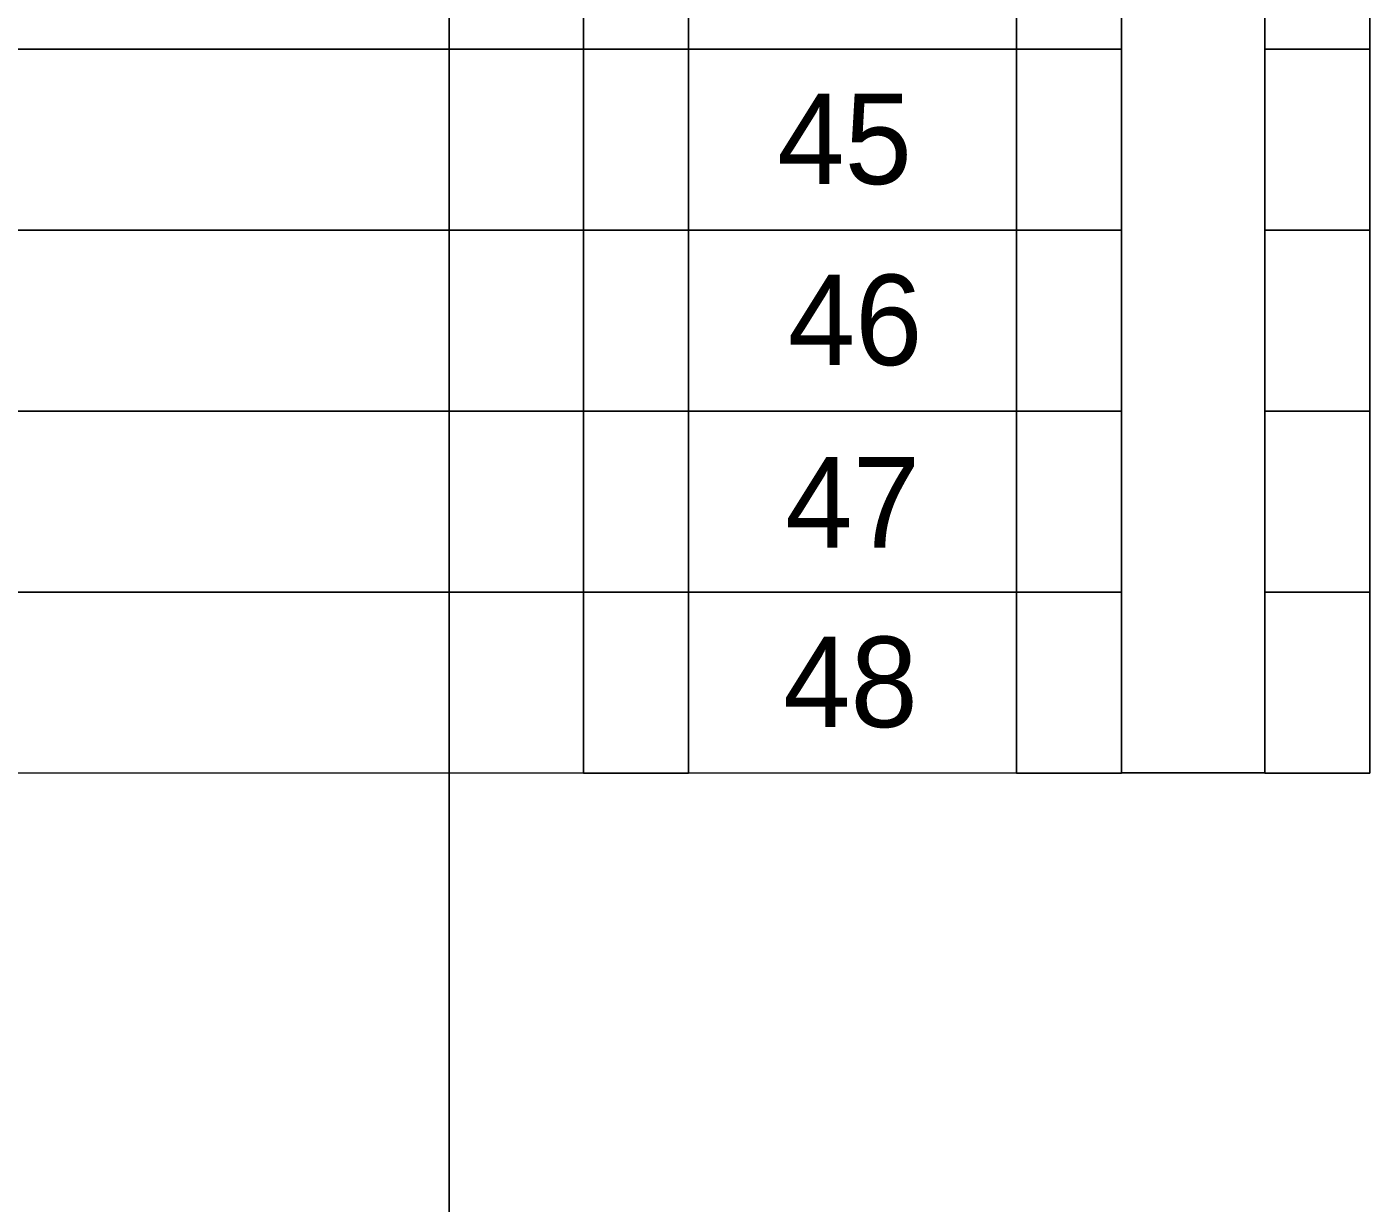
# Model space of a CAD drawing. Extents: x 1901 to 2519, y -3585 to -3154.
# Drawn here: x 2006.66 to 2032.79, y -3380.31 to -3357.44 of the extents above; entities that cross this region are included whole.
import ezdxf

# ---------------------------------------------------------------- set-up
doc = ezdxf.new("R2010")
doc.units = 0
doc.layers.add('rozvláknění', color=7, linetype='Continuous')

msp = doc.modelspace()

# ---------------------------------------------------------------- linework, layer by layer
at = {"layer": 'rozvláknění'}
for p, q in [((1933.193, -3357.872), (2025.898, -3357.874)), ((1933.193, -3361.39), (2025.898, -3361.392)), ((1933.193, -3364.908), (2025.898, -3364.91)), ((1933.193, -3368.426), (2025.898, -3368.428)), ((1933.193, -3371.945), (2025.898, -3371.947))]:
    msp.add_line(p, q, dxfattribs=at)
for points in [[(2014.869, -3178.545), (2059.522, -3178.544), (2059.522, -3570.656), (2014.869, -3570.656)], [(2019.518, -3371.947), (2017.476, -3371.947), (2017.476, -3329.728), (2019.518, -3329.728)], [(2027.939, -3329.728), (2030.726, -3329.728), (2030.726, -3371.943), (2027.939, -3371.943)], [(2025.898, -3354.356), (2027.939, -3354.356), (2027.939, -3357.874), (2025.898, -3357.874)], [(2030.726, -3354.356), (2032.767, -3354.356), (2032.767, -3357.874), (2030.726, -3357.874)], [(2030.726, -3354.356), (2032.767, -3354.356), (2032.767, -3357.874), (2030.726, -3357.874)], [(2025.898, -3357.874), (2027.939, -3357.874), (2027.939, -3361.392), (2025.898, -3361.392)], [(2030.726, -3357.874), (2032.767, -3357.874), (2032.767, -3361.392), (2030.726, -3361.392)], [(2030.726, -3357.874), (2032.767, -3357.874), (2032.767, -3361.392), (2030.726, -3361.392)], [(2025.898, -3361.392), (2027.939, -3361.392), (2027.939, -3364.91), (2025.898, -3364.91)], [(2030.726, -3361.392), (2032.767, -3361.392), (2032.767, -3364.91), (2030.726, -3364.91)], [(2030.726, -3361.392), (2032.767, -3361.392), (2032.767, -3364.91), (2030.726, -3364.91)], [(2025.898, -3364.91), (2027.939, -3364.91), (2027.939, -3368.428), (2025.898, -3368.428)], [(2030.726, -3364.91), (2032.767, -3364.91), (2032.767, -3368.428), (2030.726, -3368.428)], [(2030.726, -3364.91), (2032.767, -3364.91), (2032.767, -3368.428), (2030.726, -3368.428)], [(2025.898, -3368.428), (2027.939, -3368.428), (2027.939, -3371.947), (2025.898, -3371.947)], [(2030.726, -3368.428), (2032.767, -3368.428), (2032.767, -3371.947), (2030.726, -3371.947)], [(2030.726, -3368.428), (2032.767, -3368.428), (2032.767, -3371.947), (2030.726, -3371.947)]]:
    msp.add_lwpolyline(points, close=True, dxfattribs=at)
for points in [[(2019.518, -3329.728), (2017.476, -3329.728), (2017.476, -3371.947), (2019.518, -3371.947), (2019.518, -3329.728)], [(2019.518, -3329.728), (2017.476, -3329.728), (2017.476, -3371.947), (2019.518, -3371.947), (2019.518, -3329.728)], [(2019.518, -3329.728), (2017.476, -3329.728), (2017.476, -3371.947), (2019.518, -3371.947), (2019.518, -3329.728)], [(2019.518, -3329.728), (2017.476, -3329.728), (2017.476, -3371.947), (2019.518, -3371.947), (2019.518, -3329.728)], [(2019.518, -3329.728), (2017.476, -3329.728), (2017.476, -3371.947), (2019.518, -3371.947), (2019.518, -3329.728)], [(2019.518, -3329.728), (2017.476, -3329.728), (2017.476, -3371.947), (2019.518, -3371.947), (2019.518, -3329.728)], [(2025.898, -3357.874), (2027.939, -3357.874), (2027.939, -3354.356), (2025.898, -3354.356), (2025.898, -3357.874)], [(2025.898, -3357.874), (2027.939, -3357.874), (2027.939, -3354.356), (2025.898, -3354.356), (2025.898, -3357.874)], [(2025.898, -3357.874), (2027.939, -3357.874), (2027.939, -3354.356), (2025.898, -3354.356), (2025.898, -3357.874)], [(2025.898, -3357.874), (2027.939, -3357.874), (2027.939, -3354.356), (2025.898, -3354.356), (2025.898, -3357.874)], [(2025.898, -3357.874), (2027.939, -3357.874), (2027.939, -3354.356), (2025.898, -3354.356), (2025.898, -3357.874)], [(2025.898, -3357.874), (2027.939, -3357.874), (2027.939, -3354.356), (2025.898, -3354.356), (2025.898, -3357.874)], [(2025.898, -3357.874), (2027.939, -3357.874), (2027.939, -3354.356), (2025.898, -3354.356), (2025.898, -3357.874)], [(2025.898, -3357.874), (2027.939, -3357.874), (2027.939, -3354.356), (2025.898, -3354.356), (2025.898, -3357.874)], [(2025.898, -3357.874), (2027.939, -3357.874), (2027.939, -3354.356), (2025.898, -3354.356), (2025.898, -3357.874)], [(2025.898, -3357.874), (2027.939, -3357.874), (2027.939, -3354.356), (2025.898, -3354.356), (2025.898, -3357.874)], [(2030.726, -3357.874), (2032.767, -3357.874), (2032.767, -3354.356), (2030.726, -3354.356), (2030.726, -3357.874)], [(2030.726, -3357.874), (2032.767, -3357.874), (2032.767, -3354.356), (2030.726, -3354.356), (2030.726, -3357.874)], [(2030.726, -3357.874), (2032.767, -3357.874), (2032.767, -3354.356), (2030.726, -3354.356), (2030.726, -3357.874)], [(2030.726, -3357.874), (2032.767, -3357.874), (2032.767, -3354.356), (2030.726, -3354.356), (2030.726, -3357.874)], [(2030.726, -3357.874), (2032.767, -3357.874), (2032.767, -3354.356), (2030.726, -3354.356), (2030.726, -3357.874)], [(2030.726, -3357.874), (2032.767, -3357.874), (2032.767, -3354.356), (2030.726, -3354.356), (2030.726, -3357.874)], [(2030.726, -3357.874), (2032.767, -3357.874), (2032.767, -3354.356), (2030.726, -3354.356), (2030.726, -3357.874)], [(2030.726, -3357.874), (2032.767, -3357.874), (2032.767, -3354.356), (2030.726, -3354.356), (2030.726, -3357.874)], [(2030.726, -3357.874), (2032.767, -3357.874), (2032.767, -3354.356), (2030.726, -3354.356), (2030.726, -3357.874)], [(2030.726, -3357.874), (2032.767, -3357.874), (2032.767, -3354.356), (2030.726, -3354.356), (2030.726, -3357.874)], [(2025.898, -3361.392), (2027.939, -3361.392), (2027.939, -3357.874), (2025.898, -3357.874), (2025.898, -3361.392)], [(2025.898, -3361.392), (2027.939, -3361.392), (2027.939, -3357.874), (2025.898, -3357.874), (2025.898, -3361.392)], [(2025.898, -3361.392), (2027.939, -3361.392), (2027.939, -3357.874), (2025.898, -3357.874), (2025.898, -3361.392)], [(2025.898, -3361.392), (2027.939, -3361.392), (2027.939, -3357.874), (2025.898, -3357.874), (2025.898, -3361.392)], [(2025.898, -3361.392), (2027.939, -3361.392), (2027.939, -3357.874), (2025.898, -3357.874), (2025.898, -3361.392)], [(2025.898, -3361.392), (2027.939, -3361.392), (2027.939, -3357.874), (2025.898, -3357.874), (2025.898, -3361.392)], [(2025.898, -3361.392), (2027.939, -3361.392), (2027.939, -3357.874), (2025.898, -3357.874), (2025.898, -3361.392)], [(2025.898, -3361.392), (2027.939, -3361.392), (2027.939, -3357.874), (2025.898, -3357.874), (2025.898, -3361.392)], [(2025.898, -3361.392), (2027.939, -3361.392), (2027.939, -3357.874), (2025.898, -3357.874), (2025.898, -3361.392)], [(2025.898, -3361.392), (2027.939, -3361.392), (2027.939, -3357.874), (2025.898, -3357.874), (2025.898, -3361.392)], [(2030.726, -3361.392), (2032.767, -3361.392), (2032.767, -3357.874), (2030.726, -3357.874), (2030.726, -3361.392)], [(2030.726, -3361.392), (2032.767, -3361.392), (2032.767, -3357.874), (2030.726, -3357.874), (2030.726, -3361.392)], [(2030.726, -3361.392), (2032.767, -3361.392), (2032.767, -3357.874), (2030.726, -3357.874), (2030.726, -3361.392)], [(2030.726, -3361.392), (2032.767, -3361.392), (2032.767, -3357.874), (2030.726, -3357.874), (2030.726, -3361.392)], [(2030.726, -3361.392), (2032.767, -3361.392), (2032.767, -3357.874), (2030.726, -3357.874), (2030.726, -3361.392)], [(2030.726, -3361.392), (2032.767, -3361.392), (2032.767, -3357.874), (2030.726, -3357.874), (2030.726, -3361.392)], [(2030.726, -3361.392), (2032.767, -3361.392), (2032.767, -3357.874), (2030.726, -3357.874), (2030.726, -3361.392)], [(2030.726, -3361.392), (2032.767, -3361.392), (2032.767, -3357.874), (2030.726, -3357.874), (2030.726, -3361.392)], [(2030.726, -3361.392), (2032.767, -3361.392), (2032.767, -3357.874), (2030.726, -3357.874), (2030.726, -3361.392)], [(2030.726, -3361.392), (2032.767, -3361.392), (2032.767, -3357.874), (2030.726, -3357.874), (2030.726, -3361.392)], [(2025.898, -3364.91), (2027.939, -3364.91), (2027.939, -3361.392), (2025.898, -3361.392), (2025.898, -3364.91)], [(2025.898, -3364.91), (2027.939, -3364.91), (2027.939, -3361.392), (2025.898, -3361.392), (2025.898, -3364.91)], [(2025.898, -3364.91), (2027.939, -3364.91), (2027.939, -3361.392), (2025.898, -3361.392), (2025.898, -3364.91)], [(2025.898, -3364.91), (2027.939, -3364.91), (2027.939, -3361.392), (2025.898, -3361.392), (2025.898, -3364.91)], [(2025.898, -3364.91), (2027.939, -3364.91), (2027.939, -3361.392), (2025.898, -3361.392), (2025.898, -3364.91)], [(2025.898, -3364.91), (2027.939, -3364.91), (2027.939, -3361.392), (2025.898, -3361.392), (2025.898, -3364.91)], [(2025.898, -3364.91), (2027.939, -3364.91), (2027.939, -3361.392), (2025.898, -3361.392), (2025.898, -3364.91)], [(2025.898, -3364.91), (2027.939, -3364.91), (2027.939, -3361.392), (2025.898, -3361.392), (2025.898, -3364.91)], [(2025.898, -3364.91), (2027.939, -3364.91), (2027.939, -3361.392), (2025.898, -3361.392), (2025.898, -3364.91)], [(2025.898, -3364.91), (2027.939, -3364.91), (2027.939, -3361.392), (2025.898, -3361.392), (2025.898, -3364.91)], [(2030.726, -3364.91), (2032.767, -3364.91), (2032.767, -3361.392), (2030.726, -3361.392), (2030.726, -3364.91)], [(2030.726, -3364.91), (2032.767, -3364.91), (2032.767, -3361.392), (2030.726, -3361.392), (2030.726, -3364.91)], [(2030.726, -3364.91), (2032.767, -3364.91), (2032.767, -3361.392), (2030.726, -3361.392), (2030.726, -3364.91)], [(2030.726, -3364.91), (2032.767, -3364.91), (2032.767, -3361.392), (2030.726, -3361.392), (2030.726, -3364.91)], [(2030.726, -3364.91), (2032.767, -3364.91), (2032.767, -3361.392), (2030.726, -3361.392), (2030.726, -3364.91)], [(2030.726, -3364.91), (2032.767, -3364.91), (2032.767, -3361.392), (2030.726, -3361.392), (2030.726, -3364.91)], [(2030.726, -3364.91), (2032.767, -3364.91), (2032.767, -3361.392), (2030.726, -3361.392), (2030.726, -3364.91)], [(2030.726, -3364.91), (2032.767, -3364.91), (2032.767, -3361.392), (2030.726, -3361.392), (2030.726, -3364.91)], [(2030.726, -3364.91), (2032.767, -3364.91), (2032.767, -3361.392), (2030.726, -3361.392), (2030.726, -3364.91)], [(2030.726, -3364.91), (2032.767, -3364.91), (2032.767, -3361.392), (2030.726, -3361.392), (2030.726, -3364.91)], [(2025.898, -3368.428), (2027.939, -3368.428), (2027.939, -3364.91), (2025.898, -3364.91), (2025.898, -3368.428)], [(2025.898, -3368.428), (2027.939, -3368.428), (2027.939, -3364.91), (2025.898, -3364.91), (2025.898, -3368.428)], [(2025.898, -3368.428), (2027.939, -3368.428), (2027.939, -3364.91), (2025.898, -3364.91), (2025.898, -3368.428)], [(2025.898, -3368.428), (2027.939, -3368.428), (2027.939, -3364.91), (2025.898, -3364.91), (2025.898, -3368.428)], [(2025.898, -3368.428), (2027.939, -3368.428), (2027.939, -3364.91), (2025.898, -3364.91), (2025.898, -3368.428)], [(2025.898, -3368.428), (2027.939, -3368.428), (2027.939, -3364.91), (2025.898, -3364.91), (2025.898, -3368.428)], [(2025.898, -3368.428), (2027.939, -3368.428), (2027.939, -3364.91), (2025.898, -3364.91), (2025.898, -3368.428)], [(2025.898, -3368.428), (2027.939, -3368.428), (2027.939, -3364.91), (2025.898, -3364.91), (2025.898, -3368.428)], [(2025.898, -3368.428), (2027.939, -3368.428), (2027.939, -3364.91), (2025.898, -3364.91), (2025.898, -3368.428)], [(2025.898, -3368.428), (2027.939, -3368.428), (2027.939, -3364.91), (2025.898, -3364.91), (2025.898, -3368.428)], [(2030.726, -3368.428), (2032.767, -3368.428), (2032.767, -3364.91), (2030.726, -3364.91), (2030.726, -3368.428)], [(2030.726, -3368.428), (2032.767, -3368.428), (2032.767, -3364.91), (2030.726, -3364.91), (2030.726, -3368.428)], [(2030.726, -3368.428), (2032.767, -3368.428), (2032.767, -3364.91), (2030.726, -3364.91), (2030.726, -3368.428)], [(2030.726, -3368.428), (2032.767, -3368.428), (2032.767, -3364.91), (2030.726, -3364.91), (2030.726, -3368.428)], [(2030.726, -3368.428), (2032.767, -3368.428), (2032.767, -3364.91), (2030.726, -3364.91), (2030.726, -3368.428)], [(2030.726, -3368.428), (2032.767, -3368.428), (2032.767, -3364.91), (2030.726, -3364.91), (2030.726, -3368.428)], [(2030.726, -3368.428), (2032.767, -3368.428), (2032.767, -3364.91), (2030.726, -3364.91), (2030.726, -3368.428)], [(2030.726, -3368.428), (2032.767, -3368.428), (2032.767, -3364.91), (2030.726, -3364.91), (2030.726, -3368.428)], [(2030.726, -3368.428), (2032.767, -3368.428), (2032.767, -3364.91), (2030.726, -3364.91), (2030.726, -3368.428)], [(2030.726, -3368.428), (2032.767, -3368.428), (2032.767, -3364.91), (2030.726, -3364.91), (2030.726, -3368.428)], [(2025.898, -3371.947), (2027.939, -3371.947), (2027.939, -3368.428), (2025.898, -3368.428), (2025.898, -3371.947)], [(2025.898, -3371.947), (2027.939, -3371.947), (2027.939, -3368.428), (2025.898, -3368.428), (2025.898, -3371.947)], [(2025.898, -3371.947), (2027.939, -3371.947), (2027.939, -3368.428), (2025.898, -3368.428), (2025.898, -3371.947)], [(2025.898, -3371.947), (2027.939, -3371.947), (2027.939, -3368.428), (2025.898, -3368.428), (2025.898, -3371.947)], [(2025.898, -3371.947), (2027.939, -3371.947), (2027.939, -3368.428), (2025.898, -3368.428), (2025.898, -3371.947)], [(2025.898, -3371.947), (2027.939, -3371.947), (2027.939, -3368.428), (2025.898, -3368.428), (2025.898, -3371.947)], [(2025.898, -3371.947), (2027.939, -3371.947), (2027.939, -3368.428), (2025.898, -3368.428), (2025.898, -3371.947)], [(2025.898, -3371.947), (2027.939, -3371.947), (2027.939, -3368.428), (2025.898, -3368.428), (2025.898, -3371.947)], [(2025.898, -3371.947), (2027.939, -3371.947), (2027.939, -3368.428), (2025.898, -3368.428), (2025.898, -3371.947)], [(2025.898, -3371.947), (2027.939, -3371.947), (2027.939, -3368.428), (2025.898, -3368.428), (2025.898, -3371.947)], [(2030.726, -3371.947), (2032.767, -3371.947), (2032.767, -3368.428), (2030.726, -3368.428), (2030.726, -3371.947)], [(2030.726, -3371.947), (2032.767, -3371.947), (2032.767, -3368.428), (2030.726, -3368.428), (2030.726, -3371.947)], [(2030.726, -3371.947), (2032.767, -3371.947), (2032.767, -3368.428), (2030.726, -3368.428), (2030.726, -3371.947)], [(2030.726, -3371.947), (2032.767, -3371.947), (2032.767, -3368.428), (2030.726, -3368.428), (2030.726, -3371.947)], [(2030.726, -3371.947), (2032.767, -3371.947), (2032.767, -3368.428), (2030.726, -3368.428), (2030.726, -3371.947)], [(2030.726, -3371.947), (2032.767, -3371.947), (2032.767, -3368.428), (2030.726, -3368.428), (2030.726, -3371.947)], [(2030.726, -3371.947), (2032.767, -3371.947), (2032.767, -3368.428), (2030.726, -3368.428), (2030.726, -3371.947)], [(2030.726, -3371.947), (2032.767, -3371.947), (2032.767, -3368.428), (2030.726, -3368.428), (2030.726, -3371.947)], [(2030.726, -3371.947), (2032.767, -3371.947), (2032.767, -3368.428), (2030.726, -3368.428), (2030.726, -3371.947)], [(2030.726, -3371.947), (2032.767, -3371.947), (2032.767, -3368.428), (2030.726, -3368.428), (2030.726, -3371.947)]]:
    msp.add_lwpolyline(points, dxfattribs=at)

# ---------------------------------------------------------------- texts
for s, p in [('45', (2021.248, -3360.495)), ('46', (2021.451, -3364.015)), ('47', (2021.404, -3367.565)), ('48', (2021.362, -3371.055))]:
    msp.add_text(s, height=1.76, dxfattribs=at).set_placement(p)

doc.saveas('drawing.dxf')
